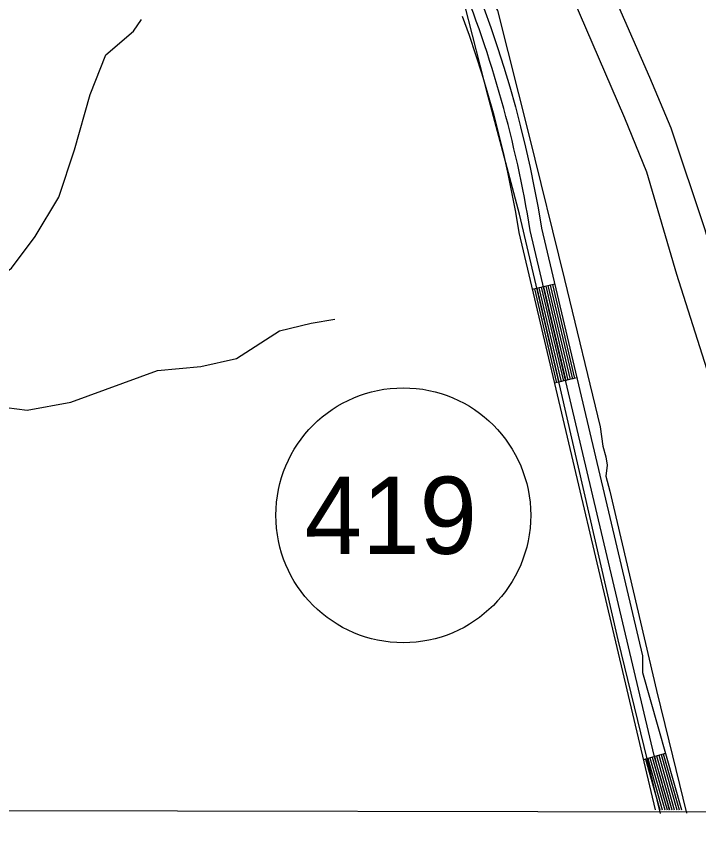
# Model space of a CAD drawing. Extents: x 3192927 to 3230760, y 831141 to 856475.
# Drawn here: x 3205416 to 3206299, y 836487 to 837559 of the extents above; entities that cross this region are included whole.
import ezdxf

# ---------------------------------------------------------------- set-up
doc = ezdxf.new("R2010")
doc.units = 0
for name, color, linetype in [('V-GRID-FRAM', 7, 'Continuous'), ('V-LEVE-TOET', 7, 'Continuous'), ('V-ROAD-CNTR', 7, 'Continuous'), ('V-ROAD-IDEN', 7, 'Continuous'), ('V-TOPO-SHOR', 7, 'Continuous')]:
    doc.layers.add(name, color=color, linetype=linetype)

msp = doc.modelspace()

# ---------------------------------------------------------------- linework, layer by layer
at = {"layer": 'V-GRID-FRAM'}
msp.add_lwpolyline([(3197144.3, 854733.3), (3228527.7, 854674), (3228501.2, 836486.7), (3197102, 836546.1), (3197144.3, 854733.3)], dxfattribs=at)
at = {"layer": 'V-LEVE-TOET'}
for points in [[(3205496.9, 838721.8), (3205634.7, 838484.3), (3205738.4, 838333), (3205835.9, 838187.2), (3205954.8, 837975.3), (3206035.8, 837807.2), (3206136.5, 837582.7), (3206203.5, 837427.6), (3206231.9, 837357.6), (3206270.7, 837224.9), (3206388.4, 836856), (3206463.1, 836592.4), (3206477.7, 836552.5), (3206481.1, 836528.4)], [(3206532.1, 836528.3), (3206531.6, 836532.3), (3206523.7, 836580.6), (3206507.4, 836632.1), (3206413.5, 836916.3), (3206308, 837282.4), (3206264, 837414), (3206236.2, 837479.8), (3206163.7, 837645.5), (3206007.7, 837969.1), (3205866.2, 838237), (3205720.5, 838521.7), (3205612.7, 838703.2)]]:
    msp.add_lwpolyline(points, dxfattribs=at)
at = {"layer": 'V-ROAD-CNTR'}
for p, q in [((3206113.2, 837212.3), (3206084, 837205.4)), ((3206141.9, 837090.7), (3206112.7, 837083.8)), ((3206256.6, 836604.7), (3206227.7, 836596.5))]:
    msp.add_line(p, q, dxfattribs=at)
for points in [[(3206021.5, 837569.6), (3206030.5, 837544.4), (3206039.2, 837518.8), (3206047.3, 837493.3), (3206055.1, 837467.6), (3206062.2, 837441.6), (3206069, 837415.8), (3206075.4, 837389.6), (3206081.2, 837363.3), (3206086.7, 837337.1), (3206091.7, 837310.8), (3206096.1, 837284.8), (3206226.8, 836730.8), (3206226.8, 836709.5), (3206277.4, 836531.4)], [(3205993.3, 837559.3), (3206002.2, 837534.5), (3206010.7, 837509.4), (3206018.7, 837484.4), (3206026.2, 837459.3), (3206033.2, 837433.8), (3206039.9, 837408.4), (3206046.2, 837382.8), (3206051.9, 837357), (3206057.3, 837331.2), (3206062.2, 837305.5), (3206066.6, 837278.9), (3206243, 836531.4)], [(3206241.8, 836601.9), (3206081.3, 837281.8)], [(3206107.3, 837210.9), (3206136, 837089.3)], [(3206110.2, 837211.6), (3206138.9, 837090)], [(3206086.9, 837206.1), (3206115.6, 837084.5)], [(3206089.8, 837206.8), (3206118.5, 837085.1)], [(3206092.7, 837207.5), (3206121.4, 837085.8)], [(3206095.6, 837208.2), (3206124.3, 837086.5)], [(3206098.6, 837208.9), (3206127.3, 837087.2)], [(3206101.5, 837209.6), (3206130.2, 837087.9)], [(3206104.4, 837210.3), (3206133.1, 837088.6)], [(3206239.2, 836599.8), (3206258.7, 836531.4)], [(3206242.1, 836600.6), (3206261.8, 836531.4)], [(3206245, 836601.4), (3206264.9, 836531.4)], [(3206247.9, 836602.2), (3206268, 836531.4)], [(3206250.8, 836603.1), (3206271.2, 836531.4)], [(3206253.7, 836603.9), (3206274.3, 836531.4)], [(3206230.6, 836597.3), (3206249.3, 836531.4)], [(3206233.5, 836598.1), (3206252.4, 836531.4)], [(3206236.4, 836599), (3206255.6, 836531.4)]]:
    msp.add_lwpolyline(points, dxfattribs=at)
for centre, radius, start, end in [((3204576.9, 837039.3), 1523.8, 9.1594, 22.1241), ((3227242.4, 842411), 21789.2, 195.46222, 195.65473)]:
    msp.add_arc(centre, radius, start, end, dxfattribs=at)
at = {"layer": 'V-ROAD-IDEN'}
msp.add_circle((3205917, 836912.9), 165, dxfattribs=at)
at = {"layer": 'V-TOPO-SHOR'}
for points in [[(3205445.7, 838812.4), (3205552, 838618), (3205628.1, 838489), (3205720.2, 838331.7), (3205750.3, 838275.1), (3205782.2, 838199.1), (3205812.3, 838128.5), (3205849.5, 838011.8), (3205897.3, 837884.5), (3205925.7, 837828), (3205964.6, 837739.6), (3206021.3, 837596.5), (3206039, 837566.4), (3206079.8, 837405.6), (3206125.9, 837218.2), (3206172.1, 837027.3), (3206175.6, 837002.6), (3206179.2, 836988.4), (3206180.9, 836977.8), (3206179.2, 836963.7), (3206184.5, 836944.2), (3206244.8, 836686.2), (3206260.8, 836620.8), (3206283.9, 836527.1)], [(3206250.3, 836527), (3206195.3, 836751.5), (3206120.8, 837076.8), (3206067.5, 837303), (3206026.7, 837456.8), (3205996.6, 837573.5), (3205955.8, 837672.4), (3205913.3, 837783.8), (3205893.8, 837826.2), (3205881.5, 837829.7), (3205867.3, 837826.2), (3205860.3, 837819.1), (3205839, 837813.8), (3205830.2, 837812)], [(3205333.1, 837120.6), (3205348.3, 837171.7), (3205373.8, 837207.5), (3205409.6, 837233), (3205440.2, 837273.9), (3205470.8, 837325), (3205491.2, 837386.3), (3205511.5, 837457.8), (3205531.9, 837508.9), (3205567.6, 837539.6), (3205577.8, 837554.9)], [(3205389.3, 837054.3), (3205430.1, 837049.2), (3205486.3, 837059.4), (3205598.6, 837100.4), (3205654.8, 837105.6), (3205700.8, 837115.8), (3205756.9, 837151.6), (3205797.8, 837161.8), (3205828.4, 837167)]]:
    msp.add_lwpolyline(points, dxfattribs=at)

# ---------------------------------------------------------------- texts
at = {"layer": 'V-ROAD-IDEN'}
msp.add_text('419', height=100, rotation=0.047, dxfattribs=at).set_placement((3205789.4, 836862.8))

doc.saveas('drawing.dxf')
